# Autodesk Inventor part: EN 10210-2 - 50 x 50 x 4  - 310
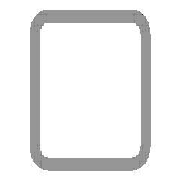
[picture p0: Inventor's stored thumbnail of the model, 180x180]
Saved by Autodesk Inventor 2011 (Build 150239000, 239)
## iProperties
IsCustomPart: 1
Created: 2020-12
Part Number: EN 10210-2 - 50 x 50 x 4  - 310
Material: Steel, Mild
Description: Tube 50*50*4
Document SubType Name: Modeling
Standard: DIN
Designer: PC
Standard Revision: 1997
Standards Organization: DIN
Language: en-US
Size Designation: 50 x 50 x 4
Categories: <MemberInstance><Categories><Category DisplayName="Structural Shapes" InternalName="089c4875-fa83-4c05-b084-43b9cc11f5ed" Mnemonic="GRDR"><CategoryParameter Dis
Stock Number: 50 x 50 x 4
Density: 7.86 g/cm^3
_CCFamilyMember: 15
_CCFamilyDisplayName: DIN EN 10219-2 (Square Hollow Section - Cold Formed) - Cold formed welded structural hollow sections of non-alloy and fine grain structural steel
_FrameMemberDoc: Frame Member File
_Version: 15.0.0
_GetPNFromCC: 1
G_L: 310.000 mm
G_W: 50.000 mm
G_H: 50.000 mm
+FBAA823C-3167-4C45-BC6E-504585FB04B4+CUTDETAIL1: Cut
Author: PC
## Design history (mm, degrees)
node "Start plane"
node "End plane"
sketch "Sketch"
  geometry: L1 (-25, -17)-(-25, 17); L2 (-17, 25)-(17, 25); L3 (25, 17)-(25, -17); L4 (17, -25)-(-17, -25); L5 (-17, 21)-(17, 21); L6 (21, 17)-(21, -17); L7 (17, -21)-(-17, -21); L8 (-21, -17)-(-21, 17); L9 (0, 37.32)-(0, -37.32) reference; L10 (-37.32, 0)-(37.32, 0) reference; A1 r 8 centre (-17, -17) between (-25, -17) and (-17, -25); A2 r 8 centre (-17, 17) between (-17, 25) and (-25, 17); A3 r 8 centre (17, 17) between (25, 17) and (17, 25); A4 r 8 centre (17, -17) between (17, -25) and (25, -17); A5 r 4 centre (-17, 17) between (-17, 21) and (-21, 17); A6 r 4 centre (17, 17) between (21, 17) and (17, 21); A7 r 4 centre (17, -17) between (17, -21) and (21, -17); A8 r 4 centre (-17, -17) between (-21, -17) and (-17, -21)
  constraints: 16 end point, 16 point on circle, 8 centre point, 8 tangent, 4 parallel, 3 equal radius, 2 perpendicular, 7 other
  dimensions: "d7" = 8 radius of A1 (= G_IR); "d10" = 50 distance between parallel lines of L2 L4 (= G_H); "d11" = 50 distance between parallel lines of L1 L3 (= G_W); "d12" = 4 distance between parallel lines of L3 L6 (= G_T); "d15" = 25 distance between parallel lines of L2 L10 (= 0.5 x d10); "d16" = 25 distance between parallel lines of L9 L3 (= 0.5 x d11)
extrude "Body" new body sketch "Sketch" stored distance "d3" = 310 (= G_L); taper "d4" = 0 deg
node "Driven Length"
  sketch "Sketch3"
    geometry: L1 (0, 0)-(10, 0) reference
    constraints: 2 end point, 1 horizontal
  workplane "Work Plane3"
  sketch "Sketch4"
    geometry: L1 (-2, 50)-(12, 50) reference; L2 (-2, 360)-(12, 360) reference
    dimensions: "d18" = 310 distance between parallel lines of L1 L2 (derived)
workplane "Work Plane4"
split "Split1"
body "Solid1"
other parameters: "G_W" = 50 [user parameter; used in 1 equation term], "G_H" = 50 [user parameter; used in 1 equation term], "G_T" = 4 [user parameter; used in 1 equation term], "G_IR" = 8 [user parameter; used in 1 equation term], "G_L" = 310 (= d18) [user parameter; used in 1 equation term], "G_OFFSET_START" = -50 [user parameter; used in 1 equation term], "G_OFFSET_END" = 0 [user parameter; used in 1 equation term], "d13" = 50 (= -G_OFFSET_START), "d17" = 90 deg
